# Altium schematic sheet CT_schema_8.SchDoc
size 391 x 238 mm
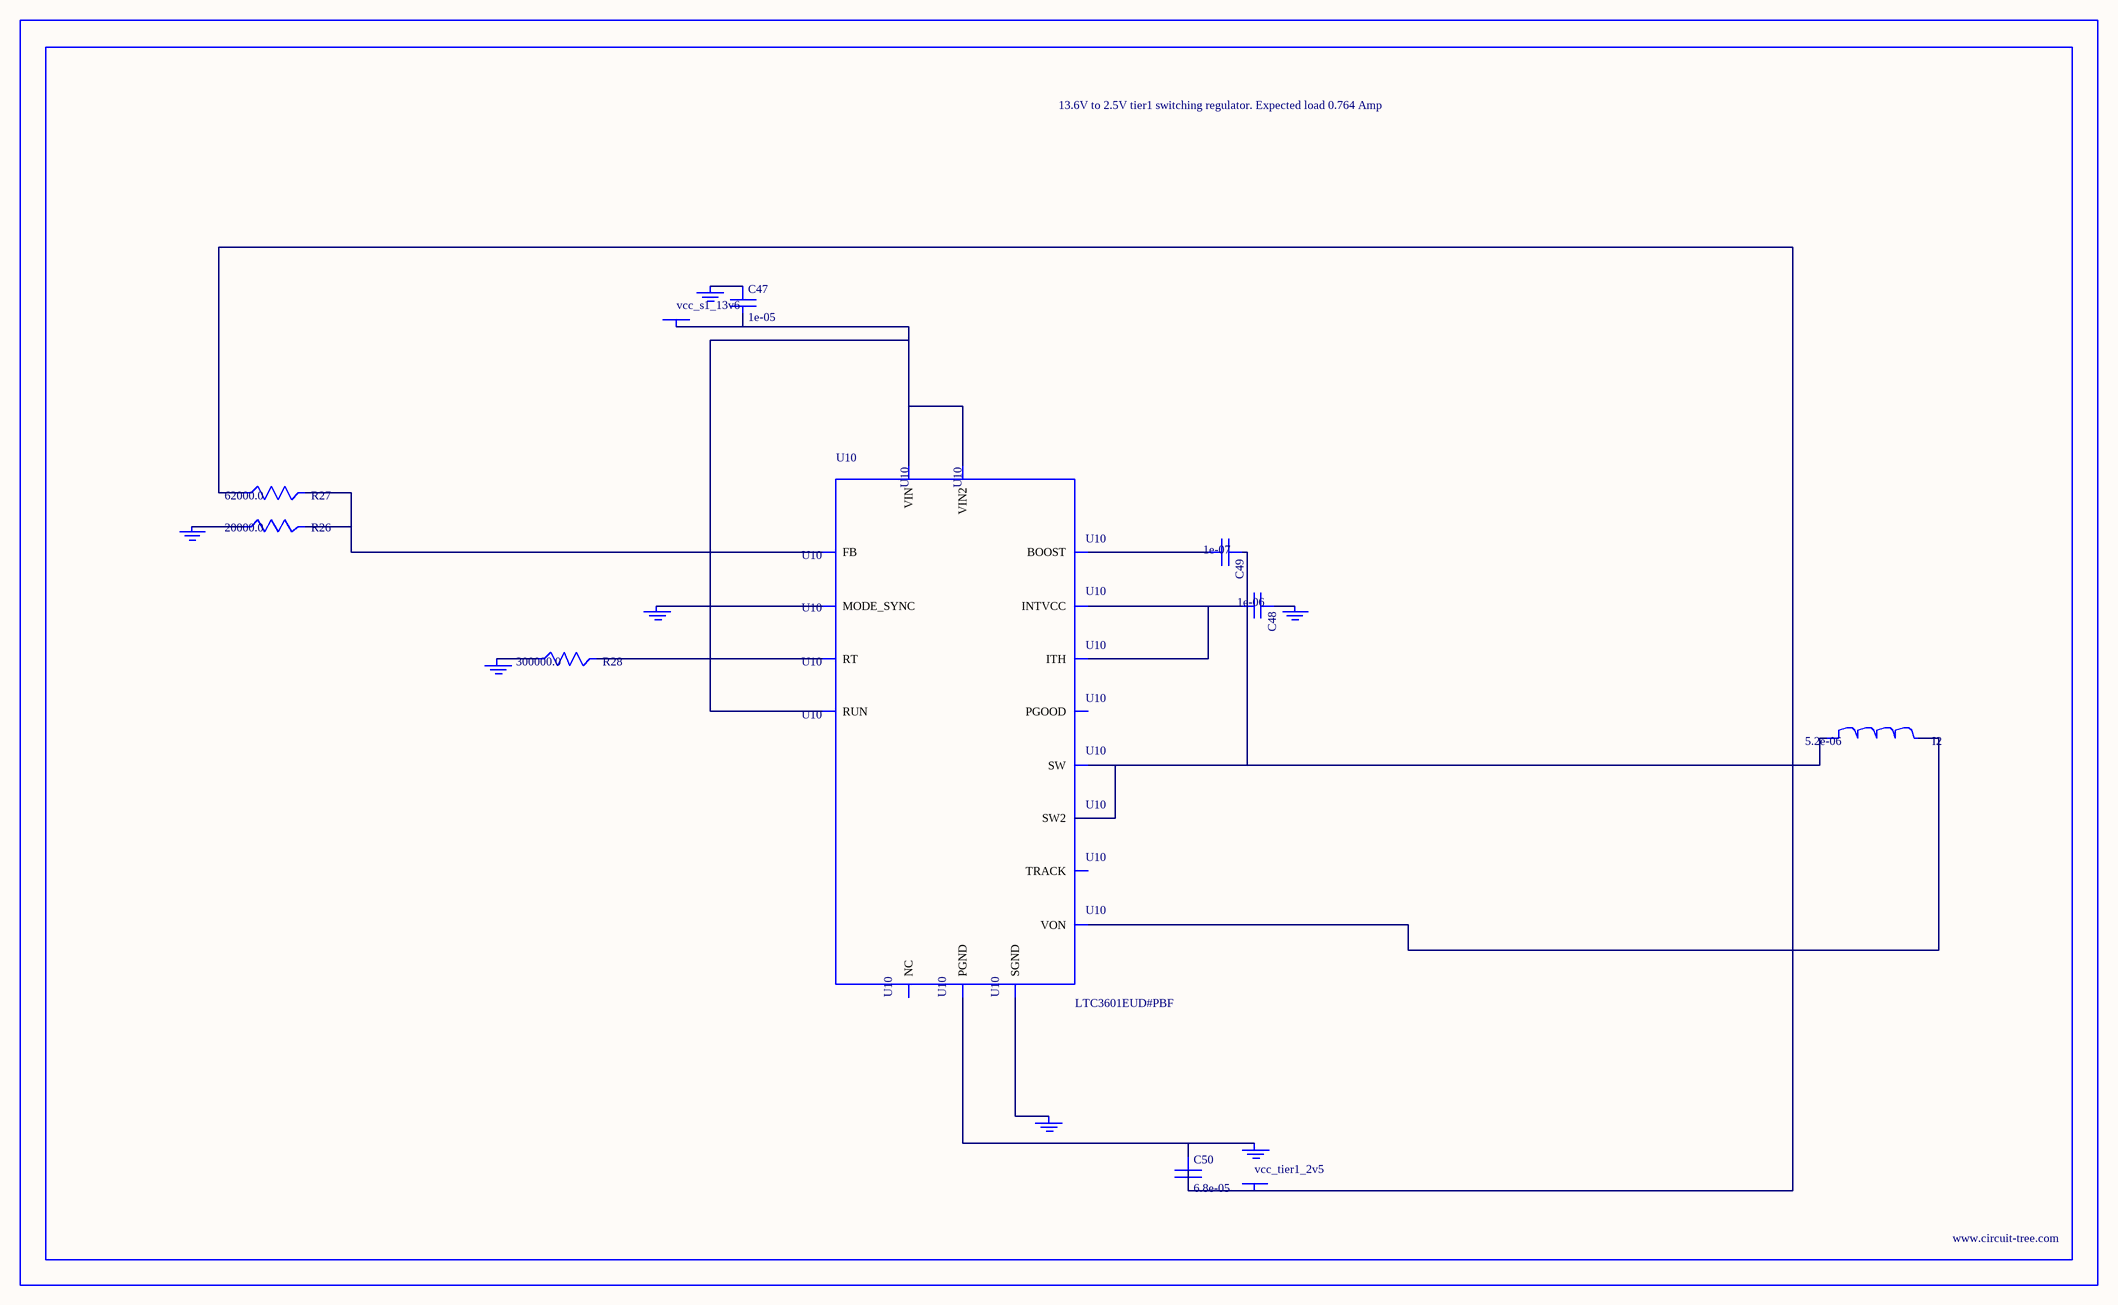
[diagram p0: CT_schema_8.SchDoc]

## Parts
BORDER7  (no value)
C47  1e-05  [C0805]
C48  1e-06  [C0603]
C49  1e-07  [C0402]
C50  6.8e-05  [2220]
GND_INSTANCE_7_0  (no value)
GND_INSTANCE_7_1  (no value)
GND_INSTANCE_7_2  (no value)
GND_INSTANCE_7_3  (no value)
GND_INSTANCE_7_4  (no value)
GND_INSTANCE_7_5  (no value)
GND_INSTANCE_7_6  (no value)
I2  5.2e-06  [DR1040]
POWER_INSTANCE_7_0  vcc_s1_13v6
POWER_INSTANCE_7_1  vcc_tier1_2v5
R26  20000.0  [R0603]
R27  62000.0  [R0603]
R28  300000.0  [R0603]
U10  LTC3601EUD#PBF  [QFN-16_EP]

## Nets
NetC47_1: C47.1 GND_INSTANCE_7_5.0(GND)
NetC47_2: C47.2 POWER_INSTANCE_7_0.0(PWR) U10.14(RUN) U10.15(VIN) U10.16(VIN2)
NetC48_1: C48.1 GND_INSTANCE_7_1.0(GND)
NetC48_2: C48.2 U10.7(INTVCC) U10.12(ITH)
NetC49_1: C49.1 I2.1 U10.3(SW) U10.4(SW2)
NetC49_2: C49.2 U10.6(BOOST)
NetC50_1: C50.1 GND_INSTANCE_7_6.0(GND) U10.17(PGND)
NetC50_2: C50.2 I2.2 POWER_INSTANCE_7_1.0(PWR) R27.1 U10.8(VON)
NetGND_INSTANCE_7_0_0: GND_INSTANCE_7_0.0(GND) U10.1(MODE_SYNC)
NetGND_INSTANCE_7_2_0: GND_INSTANCE_7_2.0(GND) U10.9(SGND)
NetGND_INSTANCE_7_3_0: GND_INSTANCE_7_3.0(GND) R28.1
NetGND_INSTANCE_7_4_0: GND_INSTANCE_7_4.0(GND) R26.1
NetR26_2: R26.2 R27.2 U10.11(FB)
NetR28_2: R28.2 U10.10(RT)

Not connected (* = marked no-connect by the designer): U10 2(PGOOD) 5(NC) 13(TRACK)

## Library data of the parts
BORDER7 = BORDER_PAGE7
C47 = C0805C106K8RACTU
C48 = C0603C105K3RACTU
C49 = C0402C104K3RACTU
C50 = C5750X5R1A686M
GND_INSTANCE_7_0-GND_INSTANCE_7_6 = GND
I2 = DR1040-5R2-R
POWER_INSTANCE_7_0 POWER_INSTANCE_7_1 = PWR
R26 = RC0603JR-0720KL
R27 = RC0603JR-0762KL
R28 = RC0603JR-07300KL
